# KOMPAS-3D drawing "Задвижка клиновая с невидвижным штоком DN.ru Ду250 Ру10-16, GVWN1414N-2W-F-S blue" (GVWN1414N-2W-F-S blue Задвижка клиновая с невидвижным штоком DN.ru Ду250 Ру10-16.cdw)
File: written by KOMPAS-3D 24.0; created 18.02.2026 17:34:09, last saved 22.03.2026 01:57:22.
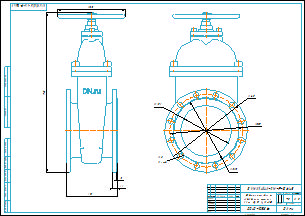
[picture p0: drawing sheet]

Document properties: Автор: R2D2; Форматы листов документа: A2; Полное имя файла: GVWN1414N-2W-F-S blue Задвижка клиновая с невидвижным штоком DN.ru Ду250 Ру10-16.m3d; Масса: 75; Наименование: Задвижка клиновая с невидвижным штоком DN.ru Ду250 Ру10-16; Количество листов документа: 1; Примечание: D040-10586

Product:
- Part/product: Задвижка клиновая с невидвижным штоком DN.ru Ду250 Ру10-16  | designation GVWN1414N-2W-F-S blue
    Масса: 75
    Раздел спецификации: Прочие изделия
    Примечание: D040-10586

Views: Вид 1, Спереди, Проекционный вид 2
Referenced files in E:\Работа\Зайцев\GVWN1414N-2W-F-S blue Задвижка клиновая с невидвижным штоком DN.ru Ду40-300 Ру10-16\DN250\: GVWN1414N-2W-F-S blue Задвижка клиновая с невидвижным штоком DN.ru Ду250 Ру10-16.m3d
Referenced files in E:\Работа\Зайцев\Для компаса\: чертеж DN.ru А3.cdt
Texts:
  GVWN1414N-2W-F-S blue
  чертеж DN.ru А3.cdt
  Задвижка клиновая с
  невидвижным штоком
  DN.ru Ду250 Ру10-16
  Задвижка клиновая с невидвижным штоком DN.ru Ду250 Ру10-16
  GVWN1414N-2W-F-S blue Задвижка клиновая с невидвижным штоком DN.ru Ду250 Ру10-16
Dimensions and other numbers on the sheet: 0; 3; 2; 4; 250; 22; 330; 780; 405; 355; 319; 28; 12 отв.; 1:2,5; 1; 75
